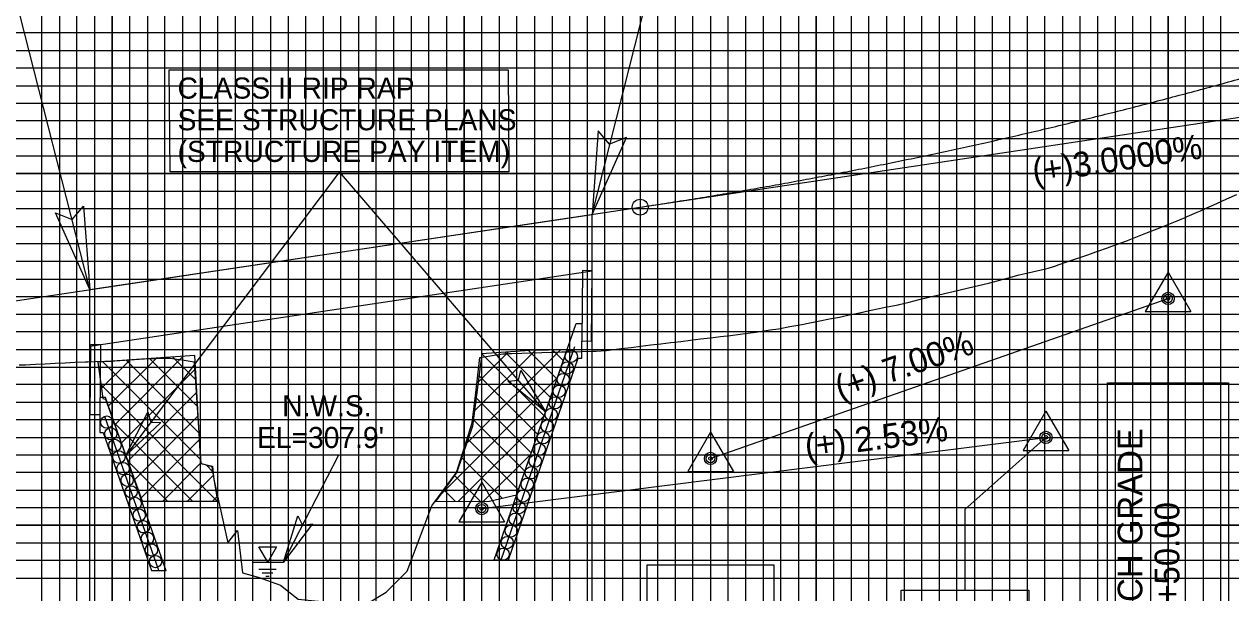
# Model space of a CAD drawing. Extents: x 574125 to 576234, y -56630 to -55530.
# Drawn here: x 575081.8 to 575424.7, y -56149.1 to -55987.3 of the extents above; entities that cross this region are included whole.
import ezdxf

# ---------------------------------------------------------------- set-up
doc = ezdxf.new("R2010")
doc.units = 0
for name, color, linetype in [('Default', 7, 'Continuous'), ('Exist Vertical Profile Ground Line', 7, 'Continuous'), ('Prop Grid Mask', 7, 'Continuous'), ('Prop PFL Text', 7, 'Continuous'), ('Prop PFL VPI Symbol CELL', 7, 'Continuous'), ('Prop Roadway Bridge', 7, 'Continuous'), ('Prop Terminator CELL', 7, 'Continuous'), ('Prop Vertical Profile Curve Label', 7, 'Continuous'), ('Prop Vertical Profile Ditch Grade Left', 7, 'Continuous'), ('Prop Vertical Profile Ditch Grade Left Label', 7, 'Continuous'), ('Prop Vertical Profile Ditch Grade Right', 7, 'Continuous'), ('Prop Vertical Profile Ditch Grade Right Label', 7, 'Continuous'), ('Prop Vertical Profile Grade', 7, 'Continuous'), ('Prop Vertical Profile Grade Label', 7, 'Continuous'), ('Prop VPI Ditch Grade Left Label', 7, 'Continuous'), ('Prop VPI Ditch Grade Right Label', 7, 'Continuous'), ('Prop VPI Label', 7, 'Continuous'), ('Sheet DOT Grid CELL', 7, 'Continuous'), ('Sheet Profile Grid Major CELL', 7, 'Continuous'), ('Sheet Profile Grid Middle CELL', 7, 'Continuous'), ('Sheet Profile Grid Minor CELL', 7, 'Continuous'), ('Typical Terminator CELL', 7, 'Continuous')]:
    doc.layers.add(name, color=color, linetype=linetype)

msp = doc.modelspace()

# ---------------------------------------------------------------- linework, layer by layer
at = {"layer": 'Default'}
for p, q in [((575146.77, -56140.35), (575155.45, -56140.35)), ((575148.44, -56142.33), (575153.44, -56142.33)), ((575149.44, -56143.33), (575152.44, -56143.33)), ((575150.44, -56144.33), (575151.44, -56144.33))]:
    msp.add_line(p, q, dxfattribs=at)
msp.add_lwpolyline([(575148.51, -56135.97), (575153.51, -56135.97), (575151.01, -56140.3)], close=True, dxfattribs=at)
at = {"layer": 'Exist Vertical Profile Ground Line'}
for points in [[(575211.29, -56082.15), (575211.93, -56082.05), (575214.75, -56081.6), (575217.85, -56081.11), (575218.34, -56081.06), (575219.47, -56081.04), (575220.39, -56081.01), (575223.21, -56080.92), (575226.04, -56080.83), (575228.86, -56080.73), (575231.68, -56080.64), (575232.73, -56080.61), (575234.5, -56080.56), (575237.32, -56080.5), (575240.14, -56080.43), (575242.96, -56080.36), (575244.29, -56080.33), (575245.78, -56080.23), (575247.22, -56080.13), (575248.6, -56079.96), (575251.42, -56079.61), (575254.24, -56079.27), (575257.06, -56078.92), (575259.89, -56078.57), (575262.71, -56078.23), (575265.53, -56077.89), (575266.62, -56077.76), (575268.35, -56077.55), (575271.17, -56077.21), (575273.99, -56076.87), (575276.81, -56076.53), (575279.63, -56076.2), (575282.45, -56075.86), (575285.27, -56075.49), (575288.09, -56075.12), (575288.93, -56075.01), (575290.91, -56074.72), (575293.73, -56074.31), (575296.15, -56073.96), (575296.56, -56073.88), (575299.38, -56073.35), (575302.2, -56072.81), (575302.72, -56072.71), (575305.02, -56072.27), (575307.84, -56071.72), (575310.66, -56071.18), (575313.48, -56070.63), (575314.58, -56070.42), (575316.3, -56070.04), (575319.12, -56069.42), (575321.94, -56068.8), (575324.76, -56068.18), (575326.43, -56067.82), (575327.58, -56067.6), (575330.1, -56067.13), (575330.4, -56067.06), (575333.23, -56066.37), (575336.05, -56065.69), (575338.87, -56065), (575339.69, -56064.81), (575341.69, -56064.33), (575344.51, -56063.67), (575347.33, -56063), (575350.15, -56062.34), (575352.97, -56061.68), (575355.79, -56061.02), (575356.21, -56060.92), (575358.61, -56060.26), (575361.43, -56059.49), (575364.47, -56058.65), (575367.07, -56058.06), (575369.9, -56057.42), (575372.08, -56056.93), (575372.72, -56056.73), (575374.88, -56056.05), (575375.54, -56055.83), (575378.36, -56054.85), (575381.18, -56053.88), (575384, -56052.91), (575386.31, -56052.08), (575386.82, -56051.92), (575389.64, -56050.94), (575390.82, -56050.53), (575392.46, -56049.92), (575394.83, -56049.05), (575395.28, -56048.87), (575398.1, -56047.75), (575400.92, -56046.63), (575403.74, -56045.52), (575406.57, -56044.42), (575407.54, -56044.05), (575409.39, -56043.27), (575411.7, -56042.31), (575412.21, -56042.09), (575415.03, -56040.86), (575415.99, -56040.44), (575417.85, -56039.59), (575420.67, -56038.32), (575423.49, -56037.07)], [(575423.49, -56037.07), (575426.31, -56035.82)], [(575080.4, -56084.26), (575082.18, -56084.18), (575085, -56084.04), (575087.82, -56083.91), (575090.64, -56083.77), (575093.46, -56083.64), (575096.28, -56083.5), (575099.1, -56083.37), (575099.94, -56083.33), (575101.92, -56083.27), (575104.74, -56083.2), (575106.57, -56083.15), (575107.56, -56083.09), (575110.38, -56082.92), (575113.2, -56082.74), (575116.03, -56082.56), (575118.43, -56082.41), (575118.85, -56082.41), (575121.34, -56082.36), (575121.67, -56082.35), (575123.28, -56082.33), (575124.49, -56082.49), (575127.31, -56082.86), (575130.13, -56083.38)], [(575204.67, -56114.85), (575204.67, -56114.85), (575209.11, -56100.73), (575210.16, -56092.21), (575211.29, -56082.15)], [(575130.14, -56083.38), (575131.97, -56112.3), (575135.28, -56113.04), (575135.67, -56116.85)], [(575135.67, -56116.85), (575139.67, -56134.8), (575142.47, -56131.35), (575143.87, -56143.35), (575148.27, -56144.55), (575154.67, -56146.85), (575159.67, -56150.85), (575170.17, -56151.85), (575179.67, -56151.85), (575184.67, -56148.85), (575190.67, -56142.85), (575197.67, -56124.35), (575204.67, -56114.85)]]:
    msp.add_lwpolyline(points, dxfattribs=at)
at = {"layer": 'Prop Grid Mask'}
for p, q in [((575406.81, -56065.35), (575406.81, -56089.34)), ((575349.11, -56125.35), (575372.11, -56104.85)), ((575276.81, -56110.85), (575276.81, -56141.05)), ((575211.81, -56160.12), (575211.81, -56125.1)), ((575349.11, -56125.35), (575349.11, -56148.28))]:
    msp.add_line(p, q, dxfattribs=at)
for points in [[(575123.03, -56000.34), (575219.29, -56000.33), (575219.51, -56029.38), (575123.25, -56029.39)], [(575424, -56205.39), (575389.62, -56205.39), (575389.62, -56089.34), (575424, -56089.34)], [(575294.76, -56266.92), (575258.86, -56266.92), (575258.86, -56141.05), (575294.76, -56141.05)], [(575367.27, -56265.86), (575330.95, -56265.86), (575330.95, -56148.28), (575367.27, -56148.28)]]:
    msp.add_lwpolyline(points, close=True, dxfattribs=at)
at = {"layer": 'Prop PFL VPI Symbol CELL'}
for p, q in [((575406.8, -56057.87), (575400.35, -56069.07)), ((575406.8, -56057.87), (575413.3, -56069.07)), ((575400.35, -56069.07), (575413.3, -56069.07)), ((575372.1, -56097.37), (575365.65, -56108.57)), ((575372.1, -56097.37), (575378.6, -56108.57)), ((575276.8, -56103.37), (575270.35, -56114.57)), ((575276.8, -56103.37), (575283.3, -56114.57)), ((575365.65, -56108.57), (575378.6, -56108.57)), ((575270.35, -56114.57), (575283.3, -56114.57)), ((575211.8, -56117.62), (575205.35, -56128.82)), ((575211.8, -56117.62), (575218.3, -56128.82)), ((575205.35, -56128.82), (575218.3, -56128.82))]:
    msp.add_line(p, q, dxfattribs=at)
for centre, radius in [((575406.81, -56065.35), 1.75), ((575406.81, -56065.35), 1.2), ((575372.11, -56104.85), 1.75), ((575372.11, -56104.85), 1.2), ((575276.81, -56110.85), 1.75), ((575276.81, -56110.85), 1.2), ((575211.81, -56125.1), 1.75), ((575211.81, -56125.1), 1.2)]:
    msp.add_circle(centre, radius, dxfattribs=at)
at = {"layer": 'Prop Roadway Bridge'}
for p, q in [((575100.46, -56062.85), (575243.16, -56041.44)), ((575243.16, -56179.46), (575243.16, -56041.44)), ((575100.46, -56078.88), (575243.16, -56057.47)), ((575100.46, -56179.87), (575100.46, -56062.85)), ((575191.85, -56230.81), (575191.85, -56065.17)), ((575141.85, -56231.51), (575141.85, -56072.67)), ((575217.33, -56139.71), (575238.22, -56078.99)), ((575130.35, -56081.53), (575102.79, -56083.49)), ((575105.81, -56095.91), (575119.41, -56082.31)), ((575107.64, -56101.15), (575127.02, -56081.77)), ((575117.4, -56082.45), (575131.12, -56096.18)), ((575124, -56081.99), (575130.73, -56088.72)), ((575131.97, -56112.3), (575130.35, -56081.53)), ((575207.51, -56106.63), (575234.17, -56079.97)), ((575211.86, -56081.07), (575209.22, -56101.62)), ((575209.77, -56097.3), (575226.95, -56080.12)), ((575210.81, -56089.18), (575219.44, -56080.56)), ((575225.52, -56080.14), (575211.86, -56081.07)), ((575211.86, -56081.07), (575229.53, -56098.75)), ((575218.48, -56080.62), (575231.35, -56093.5)), ((575221.68, -56121.29), (575236.15, -56079.76)), ((575225.1, -56080.17), (575233.17, -56088.25)), ((575236.05, -56079.93), (575225.52, -56080.14)), ((575232.01, -56080.02), (575234.99, -56082.99)), ((575102.79, -56083.49), (575104.19, -56093.79)), ((575103.79, -56090.86), (575111.8, -56082.85)), ((575104.19, -56083.39), (575131.91, -56111.11)), ((575109.47, -56106.39), (575130.55, -56085.31)), ((575110.79, -56082.92), (575131.52, -56103.64)), ((575199.96, -56121.25), (575233.28, -56087.93)), ((575211.05, -56087.34), (575227.71, -56104)), ((575103.67, -56089.93), (575136.69, -56122.96)), ((575111.3, -56111.64), (575130.91, -56092.03)), ((575104.19, -56093.79), (575104.89, -56094.02)), ((575104.89, -56094.02), (575115.45, -56123.16)), ((575210.25, -56093.6), (575225.9, -56109.25)), ((575120.04, -56142.7), (575104.69, -56098.87)), ((575113.13, -56116.88), (575131.26, -56098.75)), ((575205.26, -56123.02), (575229.53, -56098.75)), ((575107.55, -56100.89), (575129.62, -56122.96)), ((575209.22, -56101.62), (575204.75, -56114.71)), ((575209.44, -56099.87), (575224.05, -56114.48)), ((575114.96, -56122.12), (575131.61, -56105.47)), ((575207.92, -56105.42), (575222.22, -56119.72)), ((575212.35, -56123.01), (575225.75, -56109.6)), ((575111.34, -56111.75), (575122.55, -56122.96)), ((575121.19, -56122.96), (575131.96, -56112.18)), ((575135.22, -56113.27), (575131.97, -56112.3)), ((575133.58, -56112.78), (575135.45, -56114.65)), ((575136.88, -56122.96), (575135.22, -56113.27)), ((575206.12, -56110.7), (575217.58, -56122.15)), ((575128.26, -56122.96), (575135.62, -56115.6)), ((575204.75, -56114.71), (575198.65, -56123.04)), ((575204.04, -56115.68), (575211.37, -56123.01)), ((575201.05, -56119.76), (575204.31, -56123.02)), ((575115.37, -56122.96), (575136.88, -56122.96)), ((575135.33, -56122.96), (575136.65, -56121.64)), ((575198.65, -56123.04), (575213.99, -56123)), ((575213.99, -56123), (575221.72, -56121.16))]:
    msp.add_line(p, q, dxfattribs=at)
for points in [[(575240.21, -56077.44), (575242.96, -56077.47), (575243.16, -56057.47), (575240.41, -56057.44)], [(575100.76, -56078.45), (575103.51, -56078.48), (575103.31, -56098.48), (575100.56, -56098.45)]]:
    msp.add_lwpolyline(points, close=True, dxfattribs=at)
for points in [[(575215.35, -56139.7), (575238.65, -56072.43), (575240.26, -56072.44), (575240.16, -56082.44), (575239.16, -56082.43), (575219.31, -56139.73), (575215.35, -56139.7)], [(575122.17, -56142.8), (575104.97, -56093.5), (575103.36, -56093.48), (575103.27, -56103.48), (575104.27, -56103.49), (575117.96, -56142.7), (575122.12, -56142.7)]]:
    msp.add_lwpolyline(points, dxfattribs=at)
for centre in [(575237.26, -56081.8), (575236.12, -56085.11), (575234.98, -56088.42), (575233.84, -56091.72), (575232.7, -56095.03), (575105.27, -56100.52), (575231.57, -56098.34), (575106.43, -56103.82), (575230.43, -56101.65), (575107.58, -56107.13), (575228.15, -56108.27), (575229.29, -56104.96), (575108.74, -56110.43), (575227.01, -56111.58), (575109.9, -56113.73), (575225.87, -56114.89), (575111.05, -56117.04), (575224.73, -56118.2), (575112.21, -56120.34), (575223.59, -56121.51), (575113.37, -56123.64), (575222.45, -56124.82), (575114.52, -56126.95), (575221.32, -56128.13), (575115.68, -56130.25), (575220.18, -56131.44), (575116.84, -56133.55), (575219.04, -56134.75), (575117.99, -56136.86), (575217.9, -56138.06), (575119.15, -56140.16)]:
    msp.add_circle(centre, 1.75, dxfattribs=at)
at = {"layer": 'Prop Terminator CELL'}
for points in [[(575222.91, -56085.83), (575229.94, -56097.59), (575219.27, -56088.86), (575222.22, -56088.6)], [(575120.69, -56100.58), (575110.72, -56109.97), (575116.96, -56097.68), (575117.84, -56100.5)], [(575163.71, -56129.41), (575155.45, -56140.35), (575159.54, -56127.18), (575160.89, -56129.82)]]:
    msp.add_lwpolyline(points, close=True, dxfattribs=at)
at = {"layer": 'Prop Vertical Profile Curve Label'}
msp.add_circle((575256.81, -56039.4), 2.25, dxfattribs=at)
at = {"layer": 'Prop Vertical Profile Ditch Grade Left'}
msp.add_line((575276.81, -56110.85), (575406.81, -56065.35), dxfattribs=at)
at = {"layer": 'Prop Vertical Profile Ditch Grade Right'}
msp.add_line((575211.81, -56125.1), (575372.11, -56104.85), dxfattribs=at)
at = {"layer": 'Prop Vertical Profile Grade'}
msp.add_line((575064.31, -56068.27), (575256.81, -56039.4), dxfattribs=at)
msp.add_spline([(575256.81, -56039.4), (575263.81, -56038.33), (575270.81, -56037.22), (575277.81, -56036.08), (575284.81, -56034.9), (575291.81, -56033.69), (575298.81, -56032.43), (575305.81, -56031.14), (575312.81, -56029.82), (575319.81, -56028.45), (575326.81, -56027.05), (575333.81, -56025.61), (575340.81, -56024.14), (575347.81, -56022.63), (575354.81, -56021.08), (575361.81, -56019.49), (575368.81, -56017.87), (575375.81, -56016.21), (575382.81, -56014.51), (575389.81, -56012.78), (575396.81, -56011.01), (575403.81, -56009.2), (575410.81, -56007.36), (575417.81, -56005.48), (575424.81, -56003.56), (575431.81, -56001.61), (575438.81, -55999.61), (575445.81, -55997.58), (575452.81, -55995.52), (575459.81, -55993.42), (575466.81, -55991.28), (575473.81, -55989.1), (575480.81, -55986.89), (575487.81, -55984.64), (575494.81, -55982.35), (575501.81, -55980.02), (575508.81, -55977.66), (575515.81, -55975.27), (575522.81, -55972.83), (575529.81, -55970.36), (575536.81, -55967.85), (575543.81, -55965.3), (575550.81, -55962.72), (575557.81, -55960.1), (575564.81, -55957.44), (575571.81, -55954.75), (575578.81, -55952.02), (575585.81, -55949.25), (575592.81, -55946.45), (575599.81, -55943.61), (575606.81, -55940.73)], degree=3, dxfattribs=at)
at = {"layer": 'Prop VPI Ditch Grade Left Label'}
for centre in [(575406.81, -56065.35), (575276.81, -56110.85)]:
    msp.add_circle(centre, 0.5, dxfattribs=at)
at = {"layer": 'Prop VPI Ditch Grade Right Label'}
for centre in [(575372.11, -56104.85), (575211.81, -56125.1)]:
    msp.add_circle(centre, 0.5, dxfattribs=at)
at = {"layer": 'Prop VPI Label'}
for p, q in [((575243.16, -56041.44), (575288.55, -55862.58)), ((575100.46, -56062.85), (575071.74, -55949.7)), ((575256.81, -56039.4), (575429.09, -56013.56)), ((575171.38, -56029.39), (575110.72, -56109.97)), ((575229.94, -56097.59), (575171.38, -56029.39)), ((575155.45, -56140.35), (575171.12, -56109.97))]:
    msp.add_line(p, q, dxfattribs=at)
at = {"layer": 'Sheet DOT Grid CELL'}
for p, q in [((575106.81, -55554.85), (575106.81, -56579.85)), ((575156.81, -55554.85), (575156.81, -56579.85)), ((575206.81, -55554.85), (575206.81, -56579.85)), ((575256.81, -55554.85), (575256.81, -56579.85)), ((575306.81, -55554.85), (575306.81, -56579.85)), ((575356.81, -55554.85), (575356.81, -56579.85)), ((575406.81, -55554.85), (575406.81, -56579.85)), ((574506.81, -56029.85), (576006.81, -56029.85)), ((574506.81, -56079.85), (576006.81, -56079.85)), ((574506.81, -56129.85), (576006.81, -56129.85))]:
    msp.add_line(p, q, dxfattribs=at)
at = {"layer": 'Sheet Profile Grid Major CELL'}
for points in [[(575056.81, -56579.85), (575106.81, -56579.85), (575106.81, -55554.85)], [(575156.81, -55554.85), (575156.81, -56579.85), (575206.81, -56579.85), (575206.81, -55554.85)], [(575256.81, -55554.85), (575256.81, -56579.85), (575306.81, -56579.85), (575306.81, -55554.85)], [(575356.81, -55554.85), (575356.81, -56579.85), (575406.81, -56579.85), (575406.81, -55554.85)], [(576006.81, -56029.85), (574506.81, -56029.85), (574506.81, -55979.85), (576006.81, -55979.85)], [(576006.81, -56129.85), (574506.81, -56129.85), (574506.81, -56079.85), (576006.81, -56079.85)]]:
    msp.add_lwpolyline(points, dxfattribs=at)
at = {"layer": 'Sheet Profile Grid Middle CELL'}
for points in [[(575131.81, -55554.85), (575131.81, -56579.85), (575181.81, -56579.85), (575181.81, -55554.85)], [(575231.81, -55554.85), (575231.81, -56579.85), (575281.81, -56579.85), (575281.81, -55554.85)], [(575331.81, -55554.85), (575331.81, -56579.85), (575381.81, -56579.85), (575381.81, -55554.85)], [(576006.81, -55954.85), (574506.81, -55954.85), (574506.81, -56004.85), (576006.81, -56004.85)], [(576006.81, -56054.85), (574506.81, -56054.85), (574506.81, -56104.85), (576006.81, -56104.85)]]:
    msp.add_lwpolyline(points, dxfattribs=at)
at = {"layer": 'Sheet Profile Grid Minor CELL'}
for points in [[(575086.81, -56579.85), (575086.81, -55554.85)], [(575091.81, -55554.85), (575091.81, -56579.85), (575096.81, -56579.85), (575096.81, -55554.85)], [(575101.81, -55554.85), (575101.81, -56579.85), (575111.81, -56579.85), (575111.81, -55554.85)], [(575116.81, -55554.85), (575116.81, -56579.85), (575116.81, -56579.85), (575121.81, -56579.85), (575121.81, -55554.85)], [(575126.81, -55554.85), (575126.81, -56579.85), (575136.81, -56579.85), (575136.81, -55554.85)], [(575141.81, -55554.85), (575141.81, -56579.85), (575146.81, -56579.85), (575146.81, -55554.85)], [(575151.81, -55554.85), (575151.81, -56579.85), (575161.81, -56579.85), (575161.81, -55554.85)], [(575166.81, -55554.85), (575166.81, -56579.85), (575171.81, -56579.85), (575171.81, -55554.85)], [(575176.81, -55554.85), (575176.81, -56579.85), (575186.81, -56579.85), (575186.81, -55554.85)], [(575191.81, -55554.85), (575191.81, -56579.85), (575196.81, -56579.85), (575196.81, -55554.85)], [(575201.81, -55554.85), (575201.81, -56579.85), (575211.81, -56579.85), (575211.81, -55554.85)], [(575216.81, -55554.85), (575216.81, -56579.85), (575221.81, -56579.85), (575221.81, -55554.85)], [(575226.81, -55554.85), (575226.81, -56579.85), (575236.81, -56579.85), (575236.81, -55554.85)], [(575241.81, -55554.85), (575241.81, -56579.85), (575246.81, -56579.85), (575246.81, -55554.85)], [(575251.81, -55554.85), (575251.81, -56579.85), (575261.81, -56579.85), (575261.81, -55554.85)], [(575266.81, -55554.85), (575266.81, -56579.85)], [(575266.81, -56579.85), (575271.81, -56579.85), (575271.81, -55555.45)], [(575276.81, -55555.45), (575276.81, -56579.85), (575286.81, -56579.85), (575286.81, -55554.85)], [(575291.81, -55554.85), (575291.81, -56579.85), (575296.81, -56579.85), (575296.81, -55554.85)], [(575301.81, -55554.85), (575301.81, -56579.85), (575311.81, -56579.85), (575311.81, -55554.85)], [(575316.81, -55554.85), (575316.81, -56579.85), (575321.81, -56579.85), (575321.81, -55554.85)], [(575326.81, -55554.85), (575326.81, -56579.85), (575336.81, -56579.85), (575336.81, -55554.85)], [(575341.81, -55554.85), (575341.81, -56579.85), (575346.81, -56579.85), (575346.81, -55554.85)], [(575351.81, -55554.85), (575351.81, -56579.85), (575361.81, -56579.85), (575361.81, -55554.85)], [(575366.81, -55554.85), (575366.81, -56579.85), (575371.81, -56579.85), (575371.81, -55554.85)], [(575376.81, -55554.85), (575376.81, -56579.85), (575386.81, -56579.85), (575386.81, -55554.85)], [(575391.81, -55554.85), (575391.81, -56579.85), (575396.81, -56579.85), (575396.81, -55554.85)], [(575401.81, -55554.85), (575401.81, -56579.85), (575411.81, -56579.85), (575411.81, -55554.85)], [(575416.81, -55554.85), (575416.81, -56579.85), (575421.81, -56579.85), (575421.81, -55554.85)], [(575956.81, -55989.85), (574556.81, -55989.85), (574556.81, -55994.85), (575956.81, -55994.85)], [(575956.81, -55999.85), (574556.81, -55999.85), (574556.81, -56009.85), (575956.81, -56009.85)], [(575956.81, -56014.85), (574556.81, -56014.85), (574556.81, -56019.85), (575956.81, -56019.85)], [(575956.81, -56024.85), (574556.81, -56024.85), (574556.81, -56034.85), (575956.81, -56034.85)], [(575956.81, -56039.85), (574556.81, -56039.85), (574556.81, -56044.85), (575956.81, -56044.85)], [(575956.81, -56049.85), (574556.81, -56049.85), (574556.81, -56059.85), (575956.81, -56059.85)], [(575956.81, -56064.85), (574556.81, -56064.85), (574556.81, -56069.85), (575956.81, -56069.85)], [(575956.81, -56074.85), (574556.81, -56074.85)], [(574556.81, -56084.85), (575956.81, -56084.85)], [(575956.81, -56089.85), (574556.81, -56089.85), (574556.81, -56094.85), (575956.81, -56094.85)], [(575956.81, -56099.85), (574556.81, -56099.85), (574556.81, -56109.85), (575956.81, -56109.85)], [(575956.81, -56114.85), (574556.81, -56114.85), (574556.81, -56119.85), (575956.81, -56119.85)], [(575956.81, -56124.85), (574556.81, -56124.85), (574556.81, -56134.85), (575956.81, -56134.85)], [(575956.81, -56139.85), (574556.81, -56139.85), (574556.81, -56144.85), (575956.81, -56144.85)]]:
    msp.add_lwpolyline(points, dxfattribs=at)
at = {"layer": 'Typical Terminator CELL'}
for points in [[(575244.91, -56017.73), (575243.16, -56041.44), (575252.9, -56019.59), (575248.14, -56021.49)], [(575098.7, -56039.14), (575100.46, -56062.85), (575090.71, -56040.99), (575095.48, -56042.89)]]:
    msp.add_lwpolyline(points, close=True, dxfattribs=at)

# ---------------------------------------------------------------- texts
at = {"layer": 'Prop PFL Text'}
for s, p in [('CLASS II RIP RAP', (575125.4, -56008.53)), ('SEE STRUCTURE PLANS', (575125.4, -56017.53)), ('(STRUCTURE PAY ITEM)', (575125.4, -56026.53)), ('N.W.S.', (575155.12, -56098.88)), ("EL=307.9'", (575147.95, -56107.88))]:
    msp.add_text(s, height=6, dxfattribs=at).set_placement(p)
at = {"layer": 'Prop Vertical Profile Ditch Grade Left Label'}
msp.add_text('(+) 7.00%', height=7, rotation=19.29, dxfattribs=at).set_placement((575313.67, -56094.35))
at = {"layer": 'Prop Vertical Profile Ditch Grade Right Label'}
msp.add_text('(+) 2.53%', height=7, rotation=7.291, dxfattribs=at).set_placement((575304.07, -56110.94))
at = {"layer": 'Prop Vertical Profile Grade Label'}
msp.add_text('(+)3.0000%', height=7, rotation=8.5308, dxfattribs=at).set_placement((575368.77, -56032.71))
at = {"layer": 'Prop VPI Ditch Grade Left Label'}
for s, p in [('END LT DITCH GRADE', (575399.51, -56202.6)), ('-L- STA.  18+50.00', (575410.01, -56202.6))]:
    msp.add_text(s, height=7, rotation=90, dxfattribs=at).set_placement(p)

doc.saveas('drawing.dxf')
